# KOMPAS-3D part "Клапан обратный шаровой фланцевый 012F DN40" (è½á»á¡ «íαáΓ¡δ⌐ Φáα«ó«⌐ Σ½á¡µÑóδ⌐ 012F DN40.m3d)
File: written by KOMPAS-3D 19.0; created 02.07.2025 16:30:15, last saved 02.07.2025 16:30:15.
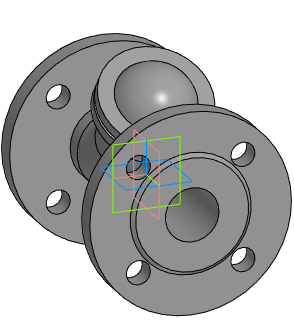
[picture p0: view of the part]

Document properties: Полное имя файла: E:\Dendor Работа Сачек\3D для проектировщиков\5.3 Тип 012F, 012F.Z Клапан обратный шаровой фланцевый\stp_Клапан обратный шаровой фланцевый 012F\Клапан обратный шаровой фланцевый 012F DN40.m3d

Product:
- Part/product: Клапан обратный шаровой фланцевый 012F DN40

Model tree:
1. Операция без истории:1  (labels: Клапан обратный шаровой фланцевый 012F DN40)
